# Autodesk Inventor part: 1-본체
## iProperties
Created: 2014-12
Part Number: 1-본체
Document SubType Name: Modeling
Designer: Administrator
Density: 2.71 g/cm^3
Material: 알루미늄-6061
Mass: 613.432 g
Surface Area: 665.172 cm^2
Volume: 226.359 cm^3
Author: Administrator
